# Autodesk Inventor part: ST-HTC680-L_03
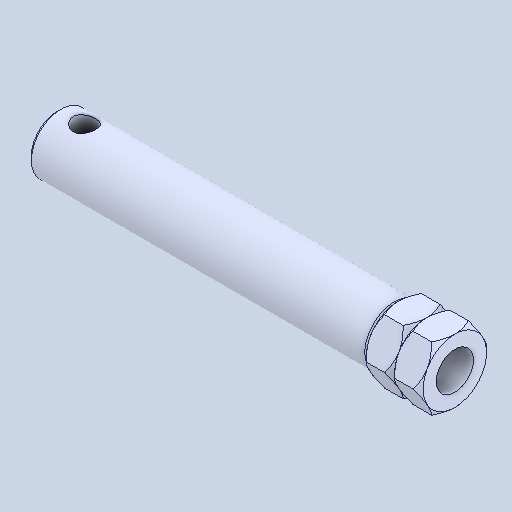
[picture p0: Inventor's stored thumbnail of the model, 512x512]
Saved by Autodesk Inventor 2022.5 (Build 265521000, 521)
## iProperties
Created: 2024-07
Part Number: ST-HTC680-L_03
Material: 一般
Document SubType Name: Modeling
Designer: ImaoCorp
Density: 1 g/cm^3
Appearance: 既定
Author: ImaoCorp
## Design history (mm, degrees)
feature "ST-HTC680-L_03"
node "ソリッド1"
